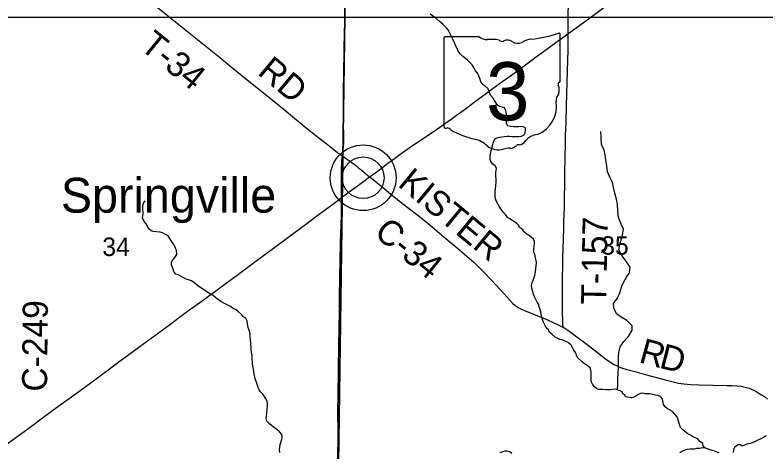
# Model space of a CAD drawing. Extents: x 0 to 34, y 0 to 22.
# Drawn here: x 2.995 to 4.694, y 15.287 to 16.277 of the extents above; entities that cross this region are included whole.
import ezdxf

# ---------------------------------------------------------------- set-up
doc = ezdxf.new("R2010")
doc.units = 0
for name, color, linetype in [('GM_X_County_Road', 7, 'Continuous'), ('GM_X_County_Road_Text', 7, 'Continuous'), ('GM_X_Minor_River', 7, 'Continuous'), ('GM_X_Section', 7, 'Continuous'), ('GM_X_Section_Text', 7, 'Continuous'), ('GM_X_State_Location', 7, 'Continuous'), ('GM_X_State_Route', 7, 'Continuous'), ('GM_X_State_Shield', 7, 'Continuous'), ('GM_X_Township_Road', 7, 'Continuous'), ('GM_X_Township_Road_Text', 7, 'Continuous'), ('GM_X_Unincorporated', 7, 'Continuous'), ('GM_X_Unincorporated_Location', 7, 'Continuous'), ('GM_X_Unincorporated_Text', 7, 'Continuous')]:
    doc.layers.add(name, color=color, linetype=linetype)

msp = doc.modelspace()

# ---------------------------------------------------------------- linework, layer by layer
at = {"layer": 'GM_X_County_Road'}
for points in [[(4.2461, 16.2345), (4.2465, 16.2795), (4.2467, 16.2981), (4.2474, 16.324), (4.2475, 16.3396), (4.2478, 16.3527), (4.2481, 16.3635), (4.2481, 16.3706), (4.2483, 16.3786), (4.2483, 16.3867), (4.2484, 16.3987), (4.2487, 16.412), (4.2492, 16.4335), (4.2493, 16.446), (4.2497, 16.4677), (4.2504, 16.5174), (4.2515, 16.5857), (4.252, 16.6261), (4.2526, 16.6727), (4.2537, 16.7442), (4.2546, 16.7938), (4.2555, 16.8498), (4.2557, 16.8709)], [(3.7971, 15.9099), (3.801, 15.9067), (3.8253, 15.8873), (3.8398, 15.8756), (3.8687, 15.8521), (3.9029, 15.8252), (3.9246, 15.8079), (3.9438, 15.7923), (3.9652, 15.7744), (3.9962, 15.7486), (4.0171, 15.7301), (4.0332, 15.7156), (4.0423, 15.7072), (4.0556, 15.6941), (4.0707, 15.6785), (4.0939, 15.6535), (4.1145, 15.6303), (4.1209, 15.6234), (4.1255, 15.6192), (4.1305, 15.6154), (4.1332, 15.6137), (4.1387, 15.6108), (4.1473, 15.607), (4.1731, 15.5965), (4.1961, 15.5874), (4.2157, 15.5788), (4.2208, 15.5765), (4.2268, 15.5734), (4.2339, 15.5697), (4.2348, 15.5692)], [(4.2348, 15.5692), (4.2407, 15.566), (4.2458, 15.5625), (4.2632, 15.5501), (4.2924, 15.5278), (4.3193, 15.5067), (4.3316, 15.4972), (4.3418, 15.49), (4.3498, 15.4851), (4.3553, 15.4823), (4.361, 15.4797), (4.3668, 15.4774), (4.3788, 15.4738), (4.3968, 15.4689), (4.4238, 15.4618), (4.4656, 15.4501), (4.4837, 15.4453), (4.4959, 15.4428), (4.5082, 15.441), (4.5237, 15.4396), (4.5423, 15.4387), (4.5734, 15.4379), (4.6044, 15.4375), (4.6162, 15.4372), (4.6283, 15.4365), (4.6377, 15.4355), (4.6467, 15.4338), (4.6526, 15.4323), (4.6583, 15.4303), (4.6624, 15.4286), (4.6665, 15.4267), (4.6718, 15.4235), (4.6824, 15.4172), (4.6902, 15.4122), (4.6975, 15.4066)]]:
    msp.add_lwpolyline(points, dxfattribs=at)
at = {"layer": 'GM_X_Minor_River'}
for points in [[(3.995, 16.2005), (3.9923, 16.2062), (3.9908, 16.2107), (3.9881, 16.2153), (3.9854, 16.2218), (3.9819, 16.2294), (3.9777, 16.237), (3.975, 16.2427), (3.9712, 16.2476), (3.9632, 16.2553), (3.9544, 16.2625), (3.9471, 16.2697), (3.9391, 16.2747), (3.9341, 16.2788)], [(4.1721, 15.695), (4.1733, 15.7019), (4.174, 15.7083), (4.1744, 15.7152), (4.174, 15.7205), (4.1724, 15.7262), (4.1705, 15.7346), (4.1686, 15.7395), (4.1689, 15.7467), (4.1693, 15.7532), (4.1701, 15.7589), (4.1701, 15.7646), (4.1674, 15.7692), (4.1628, 15.7737), (4.1582, 15.7772), (4.1532, 15.7794), (4.1483, 15.784), (4.1429, 15.7905), (4.136, 15.795), (4.1345, 15.8), (4.1303, 15.8045), (4.1245, 15.808), (4.1142, 15.8148), (4.1092, 15.8182), (4.1043, 15.8247), (4.0997, 15.8293), (4.0951, 15.835), (4.0909, 15.8418), (4.087, 15.8491), (4.0832, 15.8555), (4.0821, 15.8601), (4.0813, 15.8654), (4.0813, 15.8723), (4.0812, 15.8768), (4.082, 15.8818), (4.0827, 15.8894), (4.0835, 15.8985), (4.0831, 15.9057), (4.0827, 15.911), (4.0827, 15.919), (4.0834, 15.9251), (4.0838, 15.9297), (4.0811, 15.935), (4.0761, 15.9388), (4.0715, 15.9445), (4.0696, 15.9495), (4.0696, 15.9555), (4.0707, 15.9639), (4.0749, 15.9806), (4.0764, 15.986), (4.0779, 15.9909), (4.0802, 15.9958), (4.0848, 15.9981), (4.0909, 15.9996), (4.0962, 16.0004), (4.1084, 16.0019), (4.1134, 16.0019), (4.1191, 16.0011), (4.1298, 16.0011), (4.1344, 16.0015), (4.1405, 16.0023), (4.147, 16.0053), (4.1492, 16.0099), (4.15, 16.0156), (4.1496, 16.0213), (4.1431, 16.0239), (4.1347, 16.0236), (4.1294, 16.0232), (4.1236, 16.0232), (4.116, 16.024), (4.1099, 16.0259), (4.1068, 16.0308), (4.1068, 16.0418), (4.1068, 16.0487), (4.1068, 16.0533), (4.1052, 16.0597), (4.1022, 16.0662), (4.0972, 16.0681), (4.0911, 16.0696), (4.0865, 16.0723), (4.0831, 16.0768), (4.0765, 16.0886), (4.0708, 16.0951), (4.0677, 16.1035), (4.065, 16.1092), (4.0578, 16.116), (4.0532, 16.1191), (4.049, 16.1252), (4.0471, 16.1305), (4.044, 16.1392), (4.0413, 16.1449), (4.0367, 16.1499), (4.0333, 16.156), (4.0287, 16.164), (4.0241, 16.1693), (4.0187, 16.1746), (4.0141, 16.1784), (4.008, 16.183), (4.0019, 16.1887), (3.9973, 16.1944), (3.995, 16.2005)], [(4.3572, 15.4276), (4.3584, 15.4354), (4.3587, 15.4517), (4.3594, 15.4654), (4.3598, 15.4787), (4.3605, 15.4912), (4.3604, 15.5018), (4.3611, 15.5121), (4.3637, 15.5246), (4.3724, 15.5368), (4.3833, 15.5497), (4.3912, 15.563), (4.3912, 15.5725), (4.379, 15.5843), (4.3661, 15.5922), (4.3559, 15.5994), (4.3494, 15.613), (4.3486, 15.6229), (4.3569, 15.6343), (4.3625, 15.6453), (4.3674, 15.662), (4.3723, 15.6723), (4.3783, 15.6826), (4.3847, 15.6928), (4.3865, 15.705), (4.377, 15.7194), (4.3683, 15.7311), (4.3606, 15.7444), (4.364, 15.7599), (4.3677, 15.7721), (4.3703, 15.7823), (4.3711, 15.7918), (4.3665, 15.8028), (4.36, 15.818), (4.3584, 15.832), (4.3576, 15.8483), (4.3553, 15.8597), (4.3522, 15.873), (4.3487, 15.8855), (4.3468, 15.8973), (4.3411, 15.9079), (4.335, 15.9211), (4.3334, 15.9352), (4.3314, 15.9477), (4.3303, 15.9598), (4.3276, 15.9701), (4.3215, 15.983), (4.321, 16.0008), (4.3198, 16.0126)], [(3.5949, 15.3033), (3.5972, 15.3101), (3.5983, 15.3154), (3.599, 15.3208), (3.5983, 15.3265), (3.5929, 15.3322), (3.5868, 15.3375), (3.5788, 15.3436), (3.5703, 15.3508), (3.5646, 15.3562), (3.5627, 15.3622), (3.5634, 15.3679), (3.5646, 15.3736), (3.5657, 15.3919), (3.5657, 15.398), (3.5641, 15.4033), (3.5611, 15.4086), (3.5553, 15.4174), (3.5503, 15.4227), (3.5473, 15.4276), (3.5446, 15.433), (3.5415, 15.4417), (3.5384, 15.4535), (3.5369, 15.4588), (3.535, 15.4687), (3.5342, 15.4744), (3.5322, 15.4858), (3.5319, 15.4912), (3.5315, 15.4972), (3.5311, 15.5037), (3.5299, 15.5132), (3.5291, 15.5193), (3.5283, 15.5338), (3.5275, 15.5406), (3.5271, 15.549), (3.5264, 15.5547), (3.5248, 15.563), (3.5225, 15.5687), (3.521, 15.5771), (3.5202, 15.584), (3.5171, 15.5897), (3.5114, 15.5931), (3.5072, 15.598), (3.4991, 15.6056), (3.4938, 15.6091), (3.4881, 15.6117), (3.4819, 15.6163), (3.4747, 15.6201), (3.467, 15.6235), (3.4621, 15.6266), (3.4556, 15.6304), (3.4487, 15.6357), (3.443, 15.6414), (3.4368, 15.6445), (3.4311, 15.6483), (3.4238, 15.6536), (3.4131, 15.6597), (3.4078, 15.6639), (3.4021, 15.6681), (3.3937, 15.6741), (3.3875, 15.6768), (3.3818, 15.6783), (3.3768, 15.6814), (3.3638, 15.6882), (3.3589, 15.6898), (3.3543, 15.6955), (3.3528, 15.7008), (3.3485, 15.7103), (3.3485, 15.7164), (3.3519, 15.7221), (3.3561, 15.727), (3.3607, 15.7339), (3.3603, 15.743), (3.3564, 15.7521), (3.3538, 15.7571), (3.3488, 15.7639), (3.3411, 15.7761), (3.3339, 15.7803), (3.3281, 15.7833), (3.3232, 15.7845), (3.3152, 15.7852), (3.3075, 15.786), (3.3026, 15.7875), (3.2976, 15.7925), (3.2945, 15.7974), (3.2922, 15.8027), (3.2869, 15.8092), (3.2834, 15.8172), (3.2845, 15.8267), (3.2841, 15.8381), (3.2837, 15.8449), (3.2856, 15.8503), (3.289, 15.856)], [(4.5568, 15.2955), (4.5516, 15.3008), (4.5509, 15.3058), (4.544, 15.3104), (4.5398, 15.3164), (4.534, 15.3191), (4.5295, 15.3206), (4.5233, 15.3248), (4.5172, 15.3279), (4.5103, 15.3332), (4.5054, 15.337), (4.5004, 15.3423), (4.4992, 15.3469), (4.4973, 15.3514), (4.4962, 15.3564), (4.4942, 15.3621), (4.4919, 15.3667), (4.487, 15.3731), (4.4824, 15.3785), (4.4774, 15.3811), (4.4713, 15.3845), (4.4659, 15.3887), (4.4621, 15.3944), (4.4606, 15.4017), (4.4598, 15.4074), (4.4548, 15.4127), (4.4499, 15.4146), (4.4441, 15.4154), (4.4384, 15.4169), (4.4304, 15.4184), (4.4258, 15.4184), (4.4208, 15.4188), (4.4151, 15.4196), (4.4102, 15.4192), (4.4041, 15.4161), (4.3995, 15.4131), (4.3945, 15.4108), (4.3899, 15.4097), (4.385, 15.4101), (4.3758, 15.4116), (4.3747, 15.4162), (4.3701, 15.4188), (4.3678, 15.4234), (4.362, 15.4261), (4.3575, 15.4276), (4.3517, 15.4287), (4.3468, 15.4283), (4.3414, 15.4276), (4.3365, 15.4272), (4.3319, 15.4272), (4.325, 15.428), (4.3201, 15.428), (4.3151, 15.4284), (4.3101, 15.4303), (4.3056, 15.4345), (4.3021, 15.439), (4.2994, 15.4451), (4.2986, 15.45), (4.2983, 15.4546), (4.2982, 15.4611), (4.2982, 15.4672), (4.2978, 15.4721), (4.2963, 15.477), (4.2917, 15.4809), (4.2856, 15.485), (4.2791, 15.4892), (4.2668, 15.5014), (4.2649, 15.5063), (4.263, 15.5117), (4.2592, 15.517), (4.2569, 15.5219), (4.253, 15.5284), (4.2473, 15.5341), (4.2427, 15.536), (4.2378, 15.5383), (4.2324, 15.5406), (4.2274, 15.5417), (4.2225, 15.5436), (4.2171, 15.5471), (4.2099, 15.5528), (4.2041, 15.5585), (4.2014, 15.5634), (4.1965, 15.5676), (4.1934, 15.5748), (4.1899, 15.5821), (4.1876, 15.5889), (4.1861, 15.5958), (4.1842, 15.6041), (4.1815, 15.6132), (4.1788, 15.6216), (4.1761, 15.6262), (4.1707, 15.6368), (4.1681, 15.6433), (4.1665, 15.6505), (4.1638, 15.6574), (4.1634, 15.6642), (4.1646, 15.6699), (4.1672, 15.6756), (4.1695, 15.6821), (4.171, 15.687), (4.1721, 15.695)], [(4.6943, 15.3236), (4.6882, 15.3198), (4.6833, 15.3175), (4.6756, 15.3133), (4.6688, 15.3095), (4.6638, 15.308), (4.6589, 15.3057), (4.6524, 15.305), (4.6451, 15.3019), (4.6402, 15.3), (4.6352, 15.3031), (4.6302, 15.3027), (4.6234, 15.2978), (4.6203, 15.2924), (4.6196, 15.2852)], [(3.5938, 15.2858), (3.5934, 15.2923), (3.5949, 15.3033)], [(4.5879, 15.2845), (4.5811, 15.2868), (4.5761, 15.289), (4.5677, 15.2917), (4.5616, 15.2936), (4.5558, 15.2959), (4.5509, 15.2959), (4.5436, 15.2948), (4.5368, 15.2944), (4.531, 15.2933), (4.5223, 15.2929), (4.5154, 15.2921), (4.5101, 15.2906), (4.5051, 15.2883), (4.499, 15.2849)], [(4.1189, 15.2836), (4.1139, 15.2874), (4.1086, 15.2885), (4.1033, 15.2885), (4.0979, 15.287), (4.0914, 15.2844)]]:
    msp.add_lwpolyline(points, dxfattribs=at)
at = {"layer": 'GM_X_Section'}
for points in [[(2.7176, 16.8709), (2.7146, 16.2714), (3.7413, 16.2718), (3.7435, 16.8709)], [(3.7435, 16.8709), (3.7413, 16.2718), (4.754, 16.2718), (4.7564, 16.8709)], [(2.7146, 16.2714), (3.7413, 16.2718), (3.7269, 15.2595), (2.7116, 15.2583)], [(3.7413, 16.2718), (4.754, 16.2718), (4.743, 15.2637), (3.7425, 15.2596), (3.7269, 15.2595)]]:
    msp.add_lwpolyline(points, close=True, dxfattribs=at)
at = {"layer": 'GM_X_State_Route'}
msp.add_lwpolyline([(2.9666, 15.2977), (3.0069, 15.3269), (3.0318, 15.3454), (3.0568, 15.3638), (3.0916, 15.3896), (3.1224, 15.4119), (3.1721, 15.4482), (3.1871, 15.4593), (3.2295, 15.4908), (3.252, 15.5073), (3.2746, 15.5238), (3.2996, 15.5422), (3.3472, 15.577), (3.3641, 15.59), (3.3852, 15.6054), (3.4149, 15.6268), (3.4353, 15.6421), (3.4522, 15.6543), (3.4724, 15.6689), (3.4974, 15.6873), (3.5122, 15.6987), (3.5396, 15.719), (3.5796, 15.7486), (3.612, 15.7726), (3.6516, 15.8022), (3.6774, 15.8213), (3.6965, 15.8354), (3.726, 15.8575), (3.7337, 15.8631), (3.7592, 15.8818), (3.7691, 15.8892), (3.7866, 15.9022), (3.7971, 15.9099), (3.8191, 15.926), (3.8386, 15.9408), (3.8534, 15.9517), (3.8685, 15.963), (3.8885, 15.9773), (3.9189, 15.9975), (3.9405, 16.0117), (3.9559, 16.0222), (3.9836, 16.0421), (3.9936, 16.0495), (4.0086, 16.0605), (4.0136, 16.0642), (4.0336, 16.0789), (4.0612, 16.0992), (4.0912, 16.1212), (4.1313, 16.1505), (4.1736, 16.1815), (4.2184, 16.2142), (4.2398, 16.2298), (4.2461, 16.2345), (4.2592, 16.2439), (4.2893, 16.2658), (4.3463, 16.3079)], dxfattribs=at)
at = {"layer": 'GM_X_State_Shield'}
for p, q in [((4.0446, 16.2273), (3.9674, 16.2273)), ((4.2285, 16.1276), (4.2285, 16.2323)), ((3.9648, 16.2239), (3.9648, 16.0238)), ((4.2285, 16.1276), (4.2285, 16.1276))]:
    msp.add_line(p, q, dxfattribs=at)
for centre, radius, start, end in [((3.9678, 16.2243), 0.00305, 98.1301, 188.1301), ((4.063, 16.2506), 0.0296, 231.6195, 271.1119), ((4.1346, 16.5002), 0.2796, 275.8445, 288.9065), ((4.2256, 16.2327), 0.00294, 351.8621, 97.738), ((4.0728, 16.115), 0.1064, 80.4867, 94.9883), ((4.097, 16.2254), 0.00855, 219.7921, 297.1024), ((4.1095, 16.2022), 0.0178, 54.4667, 119.1411), ((4.1325, 16.2339), 0.0214, 233.8562, 294.8282), ((4.1702, 16.1662), 0.0563, 97.3462, 120.7689), ((4.2254, 16.1272), 0.00314, 289.6038, 7.7341), ((4.2278, 16.1199), 0.00454, 107.944, 210.337), ((4.1989, 16.1067), 0.0273, 340.033, 23.6496), ((4.239, 16.0838), 0.0198, 136.8065, 186.9296), ((4.1502, 16.0705), 0.0699, 292.3089, 8.9858), ((3.9679, 16.0233), 0.00308, 171.9584, 258.3066), ((3.9683, 16.0438), 0.0235, 267.339, 280.6039), ((3.9731, 16.0122), 0.00848, 29.7484, 93.2717), ((4.0802, 16.192), 0.2019, 240.4129, 257.1985), ((4.1797, 15.9676), 0.0383, 94.4031, 142.5768), ((4.02, 15.9339), 0.0632, 47.1842, 75.836), ((4.1312, 16.0044), 0.0226, 282.8732, 323.2771), ((4.0883, 16.0112), 0.0401, 230.7004, 286.2918), ((4.1115, 15.942), 0.0329, 85.6951, 111.2099), ((4.1144, 15.9962), 0.0214, 268.777, 315.5493), ((4.1338, 15.9769), 0.00601, 65.7517, 132.6484)]:
    msp.add_arc(centre, radius, start, end, dxfattribs=at)
at = {"layer": 'GM_X_Township_Road'}
for points in [[(2.9929, 16.5508), (3.0173, 16.5315), (3.0539, 16.5027), (3.0758, 16.4853), (3.105, 16.4623), (3.1244, 16.4468), (3.1464, 16.4296), (3.1902, 16.3949), (3.2049, 16.3834), (3.2386, 16.3565), (3.3089, 16.3001), (3.3427, 16.273), (3.3888, 16.2364), (3.4567, 16.1818), (3.4802, 16.1622), (3.5239, 16.127), (3.5454, 16.1092), (3.6035, 16.0626), (3.6228, 16.0469), (3.6491, 16.025), (3.6755, 16.0037), (3.7046, 15.9808), (3.7245, 15.9654), (3.7353, 15.9577)], [(3.7353, 15.9577), (3.7359, 15.9625), (3.7378, 15.9779), (3.7385, 15.9872), (3.7387, 15.9965), (3.7386, 16.0089), (3.7382, 16.0244), (3.7377, 16.0524), (3.7378, 16.0909), (3.7379, 16.1095), (3.7384, 16.1393), (3.7396, 16.2014), (3.741, 16.2635), (3.7411, 16.2728), (3.7413, 16.2805)], [(4.2348, 15.5692), (4.2345, 15.5761), (4.2342, 15.5823), (4.2335, 15.6041), (4.2336, 15.6414), (4.2336, 15.6601), (4.2337, 15.6877), (4.2341, 15.7031), (4.2342, 15.7137), (4.2345, 15.7277), (4.2353, 15.7484), (4.2359, 15.7672), (4.2366, 15.7962), (4.2368, 15.8086), (4.2376, 15.8398), (4.239, 15.9176), (4.2393, 15.9542), (4.2402, 15.9852), (4.2405, 16.0044), (4.2414, 16.0327), (4.2423, 16.0732), (4.2429, 16.095), (4.244, 16.1292), (4.2445, 16.1447), (4.2456, 16.1789), (4.2459, 16.1914), (4.2462, 16.2119), (4.246, 16.2225), (4.2461, 16.2345)], [(3.7337, 15.8631), (3.7337, 15.8789), (3.7335, 15.8975), (3.7337, 15.9254), (3.7339, 15.941), (3.7341, 15.9471), (3.7347, 15.9533), (3.7353, 15.9577)], [(3.7353, 15.9577), (3.7396, 15.9546), (3.7522, 15.9456), (3.7651, 15.9361), (3.7695, 15.9324), (3.7719, 15.9305), (3.7818, 15.9227), (3.7925, 15.9137), (3.7971, 15.9099)], [(3.7971, 15.9099), (3.801, 15.9067), (3.8253, 15.8873), (3.8398, 15.8756), (3.8687, 15.8521), (3.9029, 15.8252), (3.9246, 15.8079), (3.9438, 15.7923), (3.9652, 15.7744), (3.9962, 15.7486), (4.0171, 15.7301), (4.0332, 15.7156), (4.0423, 15.7072), (4.0556, 15.6941), (4.0707, 15.6785), (4.0939, 15.6535), (4.1145, 15.6303), (4.1209, 15.6234), (4.1255, 15.6192), (4.1305, 15.6154), (4.1332, 15.6137), (4.1387, 15.6108), (4.1473, 15.607), (4.1731, 15.5965), (4.1961, 15.5874), (4.2157, 15.5788), (4.2208, 15.5765), (4.2268, 15.5734), (4.2339, 15.5697), (4.2348, 15.5692)], [(3.7272, 15.2566), (3.7262, 15.2611), (3.7254, 15.2673), (3.725, 15.2766), (3.7254, 15.2952), (3.7255, 15.3014), (3.7255, 15.3106), (3.7255, 15.3261), (3.7253, 15.3821), (3.7256, 15.41), (3.7267, 15.4752), (3.7275, 15.528), (3.728, 15.5653), (3.7286, 15.6057), (3.729, 15.6368), (3.7298, 15.6834), (3.7306, 15.7206), (3.7315, 15.7578), (3.7321, 15.7827), (3.7326, 15.7982), (3.7335, 15.8261), (3.7337, 15.8479), (3.7337, 15.8631)], [(4.2348, 15.5692), (4.2407, 15.566), (4.2458, 15.5625), (4.2632, 15.5501), (4.2924, 15.5278), (4.3193, 15.5067), (4.3316, 15.4972), (4.3418, 15.49), (4.3498, 15.4851), (4.3553, 15.4823), (4.361, 15.4797), (4.3668, 15.4774), (4.3788, 15.4738), (4.3968, 15.4689), (4.4238, 15.4618), (4.4656, 15.4501), (4.4837, 15.4453), (4.4959, 15.4428), (4.5082, 15.441), (4.5237, 15.4396), (4.5423, 15.4387), (4.5734, 15.4379), (4.6044, 15.4375), (4.6162, 15.4372), (4.6283, 15.4365), (4.6377, 15.4355), (4.6467, 15.4338), (4.6526, 15.4323), (4.6583, 15.4303), (4.6624, 15.4286), (4.6665, 15.4267), (4.6718, 15.4235), (4.6824, 15.4172), (4.6902, 15.4122), (4.6975, 15.4066)]]:
    msp.add_lwpolyline(points, dxfattribs=at)
at = {"layer": 'GM_X_Unincorporated'}
for radius in [0.0744, 0.0472]:
    msp.add_circle((3.7825, 15.9079), radius, dxfattribs=at)
at = {"layer": 'GM_X_Unincorporated_Location'}
msp.add_line((3.7825, 15.9079), (3.7825, 15.9079), dxfattribs=at)

# ---------------------------------------------------------------- texts
at = {"layer": 'GM_X_County_Road_Text'}
for s, height, rotation, p in [('KISTER', 0.05682, 320.3929, (3.8584, 15.8905)), ('C-34', 0.05682, 320.9237, (3.8045, 15.7783)), ('C-249', 0.05682, 89.4515, (3.0672, 15.4233)), ('R', 0.0568, 344.7757, (4.4041, 15.4903)), ('D', 0.0568, 345.669, (4.4501, 15.4779))]:
    msp.add_text(s, height=height, rotation=rotation, dxfattribs=at).set_placement(p)
at = {"layer": 'GM_X_Section_Text'}
for s, p in [('34', (3.1922, 15.7307)), ('35', (4.321, 15.7336))]:
    msp.add_text(s, height=0.04186, rotation=0, dxfattribs=at).set_placement(p)
at = {"layer": 'GM_X_State_Location'}
for s in ['s', 'r']:
    msp.add_text(s, height=0.000189, dxfattribs=at).set_placement((4.0937, 16.1105))
msp.add_text('3', height=0.000189, rotation=0, dxfattribs=at).set_placement((4.0652, 16.0967))
at = {"layer": 'GM_X_State_Shield'}
msp.add_text('3', height=0.1318, dxfattribs=at).set_placement((4.0606, 16.0379))
at = {"layer": 'GM_X_Township_Road_Text'}
for s, rotation, p in [('T-34', 321.0091, (3.2748, 16.2015)), ('RD', 320.2575, (3.5411, 16.1436)), ('T-157', 88.9101, (4.3321, 15.6203))]:
    msp.add_text(s, height=0.05682, rotation=rotation, dxfattribs=at).set_placement(p)
at = {"layer": 'GM_X_Unincorporated_Text'}
msp.add_text('Springville', height=0.078977, rotation=0, dxfattribs=at).set_placement((3.0985, 15.8289))

doc.saveas('drawing.dxf')
